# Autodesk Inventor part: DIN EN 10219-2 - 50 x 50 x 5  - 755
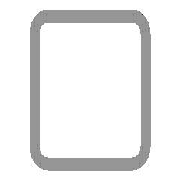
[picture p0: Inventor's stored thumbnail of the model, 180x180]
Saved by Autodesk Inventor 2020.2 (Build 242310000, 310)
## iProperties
Created: 2019-01
Part Number: DIN EN 10219-2 - 50 x 50 x 5  - 755
Material: Stahl, weich
Description: Kaltgeformte, geschweißte Baustahl-Hohlprofile aus unlegiertem Feinkorn-Baustahl
Document SubType Name: Modeling
Standard: DIN EN 10219-2
Designer: lutzd
Standard Revision: 2006-07
Standards Organization: DIN
Language: de-DE
Size Designation: 50 x 50 x 5
Categories: <MemberInstance><Categories><Category DisplayName="Profile" InternalName="089c4875-fa83-4c05-b084-43b9cc11f5ed" Mnemonic="GRDR"><CategoryParameter DisplayName="
Stock Number: 50 x 50 x 5
Mass: 4947.06 g
Surface Area: 2541.68 cm^2
Volume: 630.199 cm^3
Density: 7.85 g/cm^3
Appearance: Semi-Polished(8)
IsCustomPart: 1
G_W: 50,000 mm
G_H: 50,000 mm
+8AF67015-03BD-4175-9379-8972D13A86D3+SCHNITTDETAIL2: Schnittwinkel 90,00 grd
DocNumber: ADSK-014407
Folder: .
Mass: 4,947 kg
VLT_Material: Stahl, weich
Dimensions: 50x50x755 mm
G_L: 755,000 mm
+318D0B61-2C9B-40E8-8427-2B0BD827A7FA+SCHNITTDETAIL3: Schnittwinkel 90,00 grd
_CCFamilyMember: 16
_CCFamilyDisplayName: DIN EN 10219-2 (Quadratisches Hohlprofil - Kaltgeformt) - Kaltgeformte, geschweißte Baustahl-Hohlprofile aus unlegiertem Feinkorn-Baustahl
_FrameMemberDoc: Frame Member File
_Version: 15.0.0
_GetPNFromCC: 1
Title: Profil-Bauteil
Author: lutzd
Revision Number: -
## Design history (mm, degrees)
node "Startebene"
node "Endebene"
sketch "Skizze"
  geometry: L1 (-25, -15)-(-25, 15); L2 (-15, 25)-(15, 25); L3 (25, 15)-(25, -15); L4 (15, -25)-(-15, -25); L5 (-15, 20)-(15, 20); L6 (20, 15)-(20, -15); L7 (15, -20)-(-15, -20); L8 (-20, -15)-(-20, 15); L9 (0, 37.899)-(0, -37.899) reference; L10 (-37.899, 0)-(37.899, 0) reference; A1 r 10 centre (-15, -15) between (-25, -15) and (-15, -25); A2 r 10 centre (-15, 15) between (-15, 25) and (-25, 15); A3 r 10 centre (15, 15) between (25, 15) and (15, 25); A4 r 10 centre (15, -15) between (15, -25) and (25, -15); A5 r 5 centre (-15, 15) between (-15, 20) and (-20, 15); A6 r 5 centre (15, 15) between (20, 15) and (15, 20); A7 r 5 centre (15, -15) between (15, -20) and (20, -15); A8 r 5 centre (-15, -15) between (-20, -15) and (-15, -20)
  constraints: 16 end point, 16 point on circle, 8 centre point, 8 tangent, 4 parallel, 3 equal radius, 2 perpendicular, 7 other
  dimensions: "d7" = 10 radius of A1 (= G_IR); "d10" = 50 distance between parallel lines of L2 L4 (= G_H); "d11" = 50 distance between parallel lines of L1 L3 (= G_W); "d12" = 5 distance between parallel lines of L3 L6 (= G_T); "d15" = 25 distance between parallel lines of L2 L10 (= 0.5 x d10); "d16" = 25 distance between parallel lines of L9 L3 (= 0.5 x d11)
extrude "Körper" new body sketch "Skizze" stored distance "d3" = 755 (= G_L); taper "d4" = 0 deg
node "Driven Length"
  sketch "Sketch3"
    geometry: L1 (0, 0)-(10, 0) reference
    constraints: 2 end point, 1 horizontal
  workplane "Work Plane3"
  sketch "Sketch4"
    geometry: L1 (-2, 25)-(12, 25) reference; L2 (-2, 780)-(12, 780) reference
    dimensions: "d18" = 755 distance between parallel lines of L1 L2 (derived)
workplane "Arbeitsebene5"
feature "Trennen2"
sketch "Skizze5"
  geometry: L1 (30, 0)-(0, 0) reference; L2 (15, 0)-(15, 460); 5 further points
  constraints: 3 point on line, 2 end point, 1 coincident, 1 midpoint, 1 vertical
  dimensions: "d19" = 460 distance of L2.start L2.end; "d20" = 52 distance of point (15, 249) point (15, 301); "d21" = 52 distance of point (15, 460) point (15, 408) (= d20); "d22" = 107 distance of point (15, 408) point (15, 301)
hole "Bohrung1" sketch "Skizze5" at (15, 460), (15, 408), (15, 301), (15, 249) diameter "d23" = 6.647; stored, may be unused: countersink angle "d27" = 90 deg, drill point angle "d29" = 118 deg; dims "d24" = 16, "d25" = 17.3, "d26" = 2, "d28" = 22.2
workplane "Arbeitsebene6"
feature "Trennen3"
body "Solid1"
other parameters: "G_W" = 50 [user parameter; used in 1 equation term], "G_H" = 50 [user parameter; used in 1 equation term], "G_T" = 5 [user parameter; used in 1 equation term], "G_IR" = 10 [user parameter; used in 1 equation term], "G_L" = 755 (= d18) [user parameter; used in 1 equation term], "G_OFFSET_START" = -25 [user parameter; used in 1 equation term], "G_OFFSET_END" = -25 [user parameter; used in 1 equation term], "d13" = 25 (= -G_OFFSET_START), "B_L" = 805 [user parameter; used in 1 equation term], "d17" = 90 deg
